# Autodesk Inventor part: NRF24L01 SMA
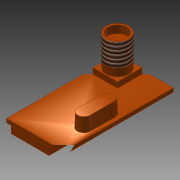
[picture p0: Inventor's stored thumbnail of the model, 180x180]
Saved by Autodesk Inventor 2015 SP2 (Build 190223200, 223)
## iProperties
Created: 2014-11
Part Number: NRF24L01 SMA
Material: Phenolharz
Document SubType Name: Modeling
Designer: rYan
Mass: 1.27162 g
Surface Area: 13.3626 cm^2
Volume: 0.921466 cm^3
Density: 1.38 g/cm^3
Appearance: Glatt - hellorange
Author: rYan
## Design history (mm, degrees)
sketch "Skizze1"
  geometry: L1 (-7.5, 29)-(7.5, 29); L2 (7.5, 29)-(7.5, 0); L3 (7.5, 0)-(-7.5, 0); L4 (-7.5, 0)-(-7.5, 29); L5 (0, 34.8)-(0, -5.8) reference; L6 (-10.5, 0)-(10.5, 0) reference; 1 further point
  constraints: 8 end point, 2 parallel, 1 collinear, 1 horizontal, 1 perpendicular, 1 other
  dimensions: "d0" = 29 distance of L3.end L1.start; "d2" = 15 distance of L1.start L1.end
extrude "Extrusion1" new body sketch "Skizze1" distance "d3" = 1; taper "d4" = 0 deg
sketch "Skizze2"
  geometry: L1 (6.9, 0.6)-(-3.1, 0.6); L2 (-3.1, 0.6)-(-3.1, 5.6); L3 (-3.1, 5.6)-(6.9, 5.6); L4 (6.9, 5.6)-(6.9, 0.6); L5 (7.5, 0)-(7.5, 29) reference; L6 (-7.5, 0)-(7.5, 0) reference; 1 further point
  constraints: 8 end point, 2 parallel, 1 horizontal, 1 perpendicular
  dimensions: "d5" = 10 distance of L2.end L3.end; "d6" = 5 distance of L1.end L2.end; "d7" = 0.6 distance between parallel lines of L4 L5; "d8" = 0.6 distance between parallel lines of L1 L6
extrude "Extrusion2" join sketch "Skizze2" distance "d9" = 2.5; taper "d10" = 0 deg
sketch "Skizze3"
  geometry: L1 (3, 14.65)-(6.5, 14.65); L2 (6.5, 14.65)-(6.5, 8.15); L3 (6.5, 8.15)-(3, 8.15); L4 (3, 8.15)-(3, 14.65); L5 (7.5, 0)-(7.5, 29) reference; L6 (-7.5, 0)-(7.5, 0) reference; A1 r 1.75 centre (4.75, 14.65) between (6.5, 14.65) and (3, 14.65); A2 r 1.75 centre (4.75, 8.15) between (3, 8.15) and (6.5, 8.15); 1 further point
  constraints: 8 end point, 4 point on circle, 2 centre point, 2 midpoint, 2 parallel, 1 horizontal, 1 perpendicular
  dimensions: "d11" = 3.5 distance of L2.end L3.end; "d12" = 6.5 distance of L1.end L2.end; "d13" = 6.4 distance edge to line of A2 L6; "d14" = 1 distance between parallel lines of L5 L2
extrude "Extrusion3" join sketch "Skizze3" distance "d15" = 3.6; taper "d16" = -2 deg
sketch "Skizze4"
  geometry: L1 (-6.25, 28)-(0.25, 28); L2 (0.25, 28)-(0.25, 21.5); L3 (0.25, 21.5)-(-6.25, 21.5); L4 (-6.25, 21.5)-(-6.25, 28); L5 (7.5, 29)-(-7.5, 29) reference; L6 (-7.5, 29)-(-7.5, 0) reference; 1 further point
  constraints: 8 end point, 2 parallel, 1 horizontal, 1 perpendicular
  dimensions: "d17" = 1 distance between parallel lines of L5 L1; "d18" = 1.25 distance between parallel lines of L6 L4; "d19" = 6.5 distance of L1.end L2.end; "d20" = 6.5 distance of L1.start L1.end
extrude "Extrusion4" join sketch "Skizze4" distance "d21" = 1.5; taper "d22" = 0 deg
sketch "Skizze5"
  geometry: L1 (0.25, 28)-(-6.25, 28) reference; L2 (-6.25, 28)-(-6.25, 21.5) reference; L3 (-6.25, 21.5)-(0.25, 21.5) reference; L4 (0.25, 21.5)-(0.25, 28) reference; L5 (-3, 28)-(-3, 21.5); L6 (0.25, 24.75)-(-6.25, 24.75); C1 r 3 at (-3, 24.75); 1 further point
  constraints: 5 midpoint, 4 end point, 1 centre point
  dimensions: "d24" = 6 diameter of C1
extrude "Extrusion5" join sketch "Skizze5" distance "d25" = 8; taper "d26" = 0 deg
feature "Gewinde1" dims "d27" = 10, "d28" = 2
sketch "Skizze6"
  geometry: C1 r 3 at (0, 0) reference; C2 r 2.5 at (0, 0); 1 further point
  constraints: 1 centre point, 1 coincident
  dimensions: "d29" = 5 diameter of C2
extrude "Extrusion6" cut sketch "Skizze6" distance "d30" = 2; taper "d31" = 0 deg
node "Volumenkörper1"
node "Projizierte Kontur1"
